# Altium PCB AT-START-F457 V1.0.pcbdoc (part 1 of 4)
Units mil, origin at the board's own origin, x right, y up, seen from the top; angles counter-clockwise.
Board outline 11593.57 x 3554 mil, 2 copper layers (Top Layer, Bottom Layer); 196 components, 231 nets, 905 pads, 932 vias.
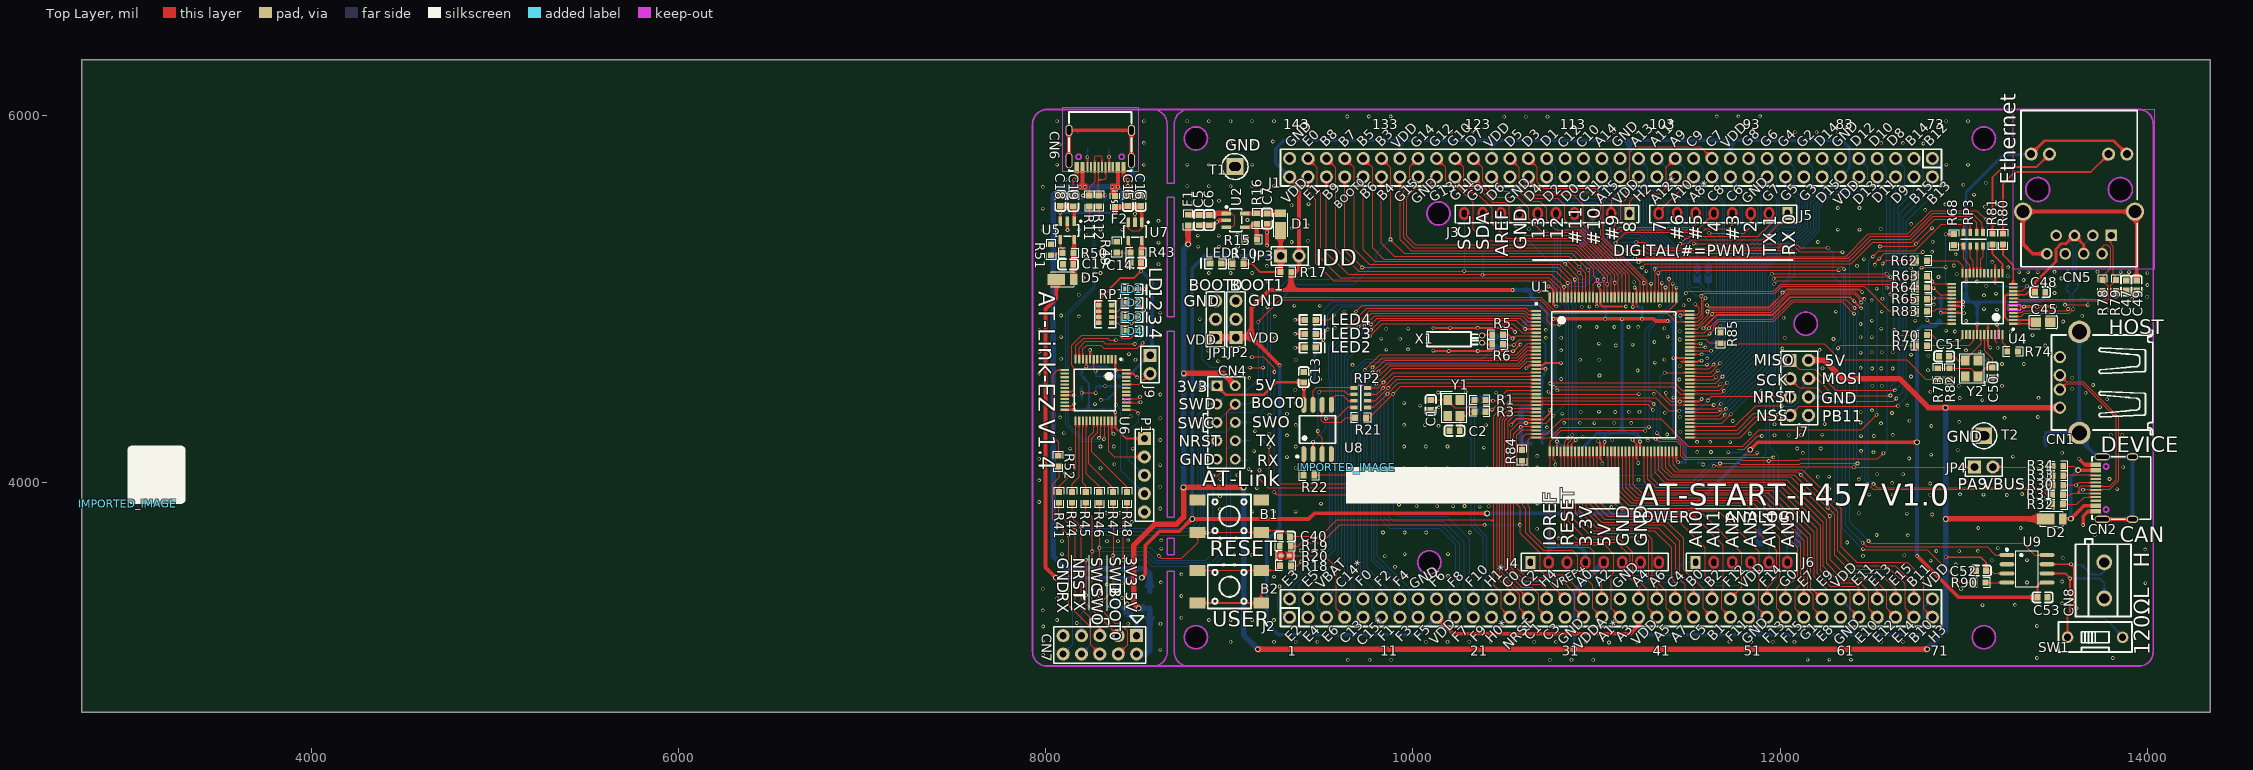
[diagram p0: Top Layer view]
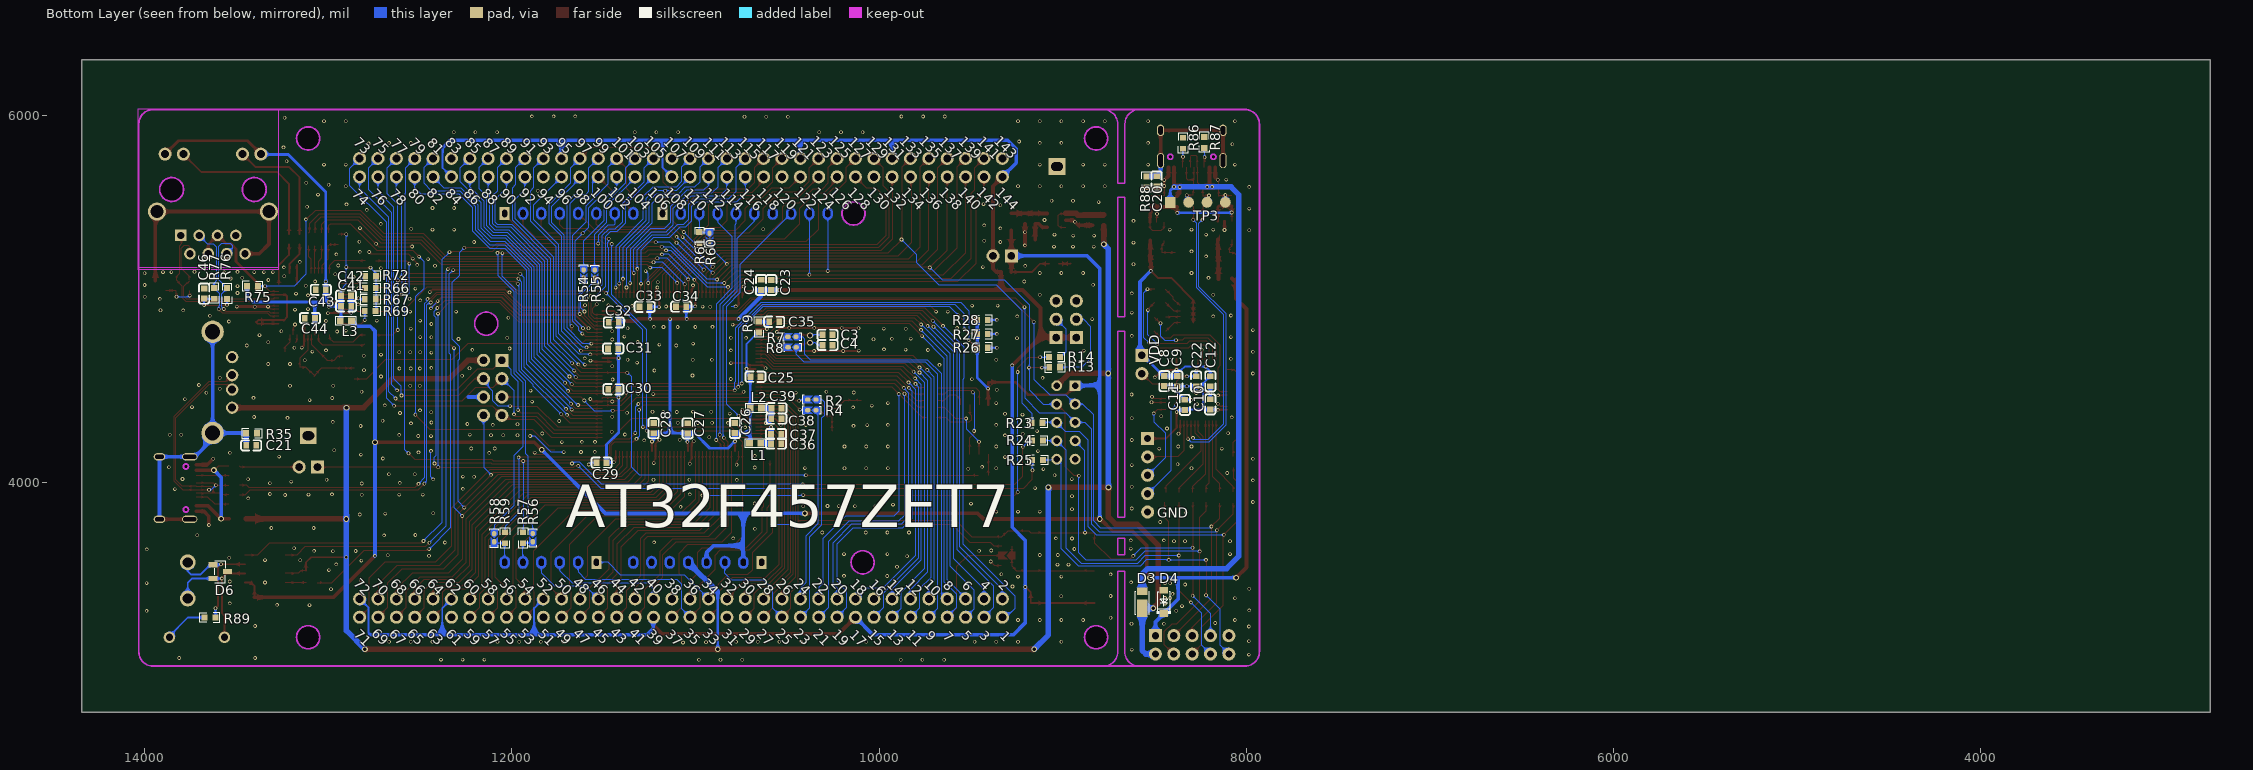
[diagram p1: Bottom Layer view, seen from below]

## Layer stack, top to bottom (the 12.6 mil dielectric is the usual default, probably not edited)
Top Layer: signal copper (thickness not stored)
Dielectric: dielectric 12.6, FR-4, Dk 4.8
Bottom Layer: signal copper (thickness not stored)

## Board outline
14343.57,2750 2750,2750 2750,6304 14343.57,6304
cut-out: 12202.8,4865.97 ccw(c12139.81,4865.43) 12076.82,4865.97 ccw(c12139.81,4866.51)
cut-out: 10202.8,5465.96 ccw(c10139.81,5465.42) 10076.82,5465.96 ccw(c10139.81,5466.5)
cut-out: 10152.8,3565.97 ccw(c10089.81,3565.43) 10026.82,3565.97 ccw(c10089.81,3566.51)
cut-out: 8881.38,5874.63 ccw(c8818.39,5874.09) 8755.4,5874.63 ccw(c8818.39,5875.17)
cut-out: 8881.38,3158.09 ccw(c8818.39,3157.55) 8755.4,3158.09 ccw(c8818.39,3158.63)
cut-out: 13172.72,3158.09 ccw(c13109.73,3157.55) 13046.74,3158.09 ccw(c13109.73,3158.63)
cut-out: 13172.72,5874.63 ccw(c13109.73,5874.09) 13046.74,5874.63 ccw(c13109.73,5875.17)

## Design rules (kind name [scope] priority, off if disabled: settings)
BoardOutlineClearance copperThickness1oz [All] p0: genericclearance=10 ignorepadtopadclearanceinfootprint=FALSE except(0: Arc-SplitContinuation Track-SplitContinuation SMDPad-SplitContinuation THPad-SplitContinuation Via-SplitContinuation Fill-SplitContinuation Poly-SplitContinuation Region-SplitContinuation Text-SplitContinuation; 6: SMDPad-CutoutEdge THPad-CutoutEdge Via-CutoutEdge Fill-CutoutEdge Region-CutoutEdge; 11.8: Track-OutlineEdge SMDPad-OutlineEdge THPad-OutlineEdge Via-OutlineEdge Fill-OutlineEdge Region-OutlineEdge Poly-OutlineEdge Text-OutlineEdge Track-CutoutEdge)
Clearance copperThickness1oz [(InNet('GND') OR InNet('PB11') OR InNet('PD4') OR InNet('PA1') OR InNet('PC1') OR InNet('PE15') OR InNet('PB10') OR InNet('PG6') OR InNet('PD10') OR InNet('PD9') OR InNet('PD8') OR InNet('PG15') OR InNet('PA2') OR InNet('PC0') OR InNet('PC2') OR InNet('NRST') OR InNet('PA15') OR InNet('PA13/SWDIO') OR InNet('PA14/SWCLK') OR InNet('VDD') OR InNet('PA3') OR InNet('PB2/BOOT1') OR InNet('3V3') OR InNet('PA0') OR InNet('PA5') OR InNet('PA6') OR InNet('PA7') OR InNet('PA9') OR InNet('PA10') OR InNet('3V3_EMAC') OR InNet('RX+') OR InNet('RX-') OR InNet('PG14') OR InNet('PG13') OR InNet('PG11') OR InNet('PB5') OR InNet('PB6') OR InNet('PD2') OR InNet('PC12') OR InNet('PC11') OR InNet('PC10') OR InNet('VBAT') OR InNet('VDDA') OR InNet('VREF+') OR InNet('PD11') OR InNet('PD12') OR InNet('PD13') OR InNet('PD14') OR InNet('PD15') OR InNet('PG2') OR InNet('PG3') OR InNet('PG4') OR InNet('PG5') OR InNet('PG7') OR InNet('PG8') OR InNet('PC6') OR InNet('PC7') OR InNet('PC8') OR InNet('PC9') OR InNet('PA8') OR InNet('PH2') OR InNet('PH0/HEXT_IN') OR InNet('PH1/HEXT_OUT') OR InNet('PF10') OR InNet('PF9') OR InNet('PF8') OR InNet('PF7') OR InNet('PF6') OR InNet('PF5') OR InNet('PF4') OR InNet('PF3') OR InNet('PF2') OR InNet('PF1') OR InNet('PF0') OR InNet('PC13') OR InNet('PE6') OR InNet('PE5') OR InNet('PE4') OR InNet('PE3') OR InNet('PE2') OR InNet('PC15/LEXT_OUT') OR InNet('PC14/LEXT_IN') OR InNet('SWO') OR InNet('ATLK_RX') OR InNet('LD4') OR InNet('VCC') OR InNet('M-NRST') OR InNet('ATLK_TX') OR InNet('ATLINK_5V') OR InNet('PH3') OR InNet('PB3') OR InNet('QSPI1_IO2') OR InNet('QSPI1_IO1') OR InNet('PB4') OR InNet('PH1_E') OR InNet('PH0_E') OR InNet('PC15_E') OR InNet('PC14_E') OR InNet('PA11_E') OR InNet('PA12_E') OR InNet('PB0') OR InNet('PA4') OR InNet('PE10') OR InNet('PC4') OR InNet('VCC3.5V') OR InNet('PG0') OR InNet('PE7') OR InNet('PE8') OR InNet('PG1') OR InNet('LD3') OR InNet('LD2') OR InNet('LD1') OR InNet('AVDD18') OR InNet('EMAC_NRST') OR InNet('TX+') OR InNet('PD3') OR InNet('PG9') OR InNet('PD6') OR InNet('REF_CLK') OR InNet('TXEN') OR InNet('TXD0') OR InNet('TXD1') OR InNet('XT1') OR InNet('RXD0') OR InNet('RXD1') OR InNet('MDIO') OR InNet('M-SWDIO') OR InNet('M-ATLK_RX') OR InNet('M-ATLK_TX') OR InNet('PE1') OR InNet('TX-') OR InNet('PC3') OR InNet('PD7') OR InNet('PG10') OR InNet('PG12') OR InNet('LED_G') OR InNet('LED_Y') OR InNet('EMAC_GND') OR InNet('M-SWCLK') OR InNet('CRS_DV') OR InNet('PC5') OR InNet('PE12') OR InNet('PE11') OR InNet('PF15') OR InNet('PF14') OR InNet('PE13') OR InNet('PE14') OR InNet('PE9') OR InNet('PF12') OR InNet('PF13') OR InNet('PB1') OR InNet('PD5') OR InNet('PE0') OR InNet('QSPI1_SCK') OR InNet('PF11') OR InNet('QSPI1_IO0') OR InNet('QSPI1_IO3') OR InNet('$2N452') OR InNet('$2N453') OR InNet('$2N511') OR InNet('$2N512') OR InNet('$2N702') OR InNet('$2N701') OR InNet('$3N82') OR InNet('$3N81') OR InNet('$3N119') OR InNet('$3N184') OR InNet('$3N504') OR InNet('$3N505') OR InNet('$3N506') OR InNet('$4N269') OR InNet('$4N270') OR InNet('$4N339') OR InNet('$5N126') OR InNet('$5N184') OR InNet('$5N573') OR InNet('$5N285') OR InNet('$5N306') OR InNet('$5N309') OR InNet('$5N310') OR InNet('$3N58') OR InNet('PA8_E') OR InNet('PA1_E') OR InNet('XT2') OR InNet('MDINTR') OR InNet('EGND1') OR InNet('OTGFS1_D-') OR InNet('OTGFS1_D+') OR InNet('PB12') OR InNet('PB13') OR InNet('PB14') OR InNet('PB15') OR InNet('PH4') OR InNet('QSPI1_CS') OR InNet('$3N17593') OR InNet('ATLK_SWCLK') OR InNet('$6N17598') OR InNet('ATLK_SWDIO') OR InNet('ATLK_BOOT0') OR InNet('ATLK_NRST') OR InNet('$6N17675') OR InNet('ATLK_SWO') OR InNet('PA11') OR InNet('PA12') OR InNet('$6N16959') OR InNet('EGND') OR InNet('$3N17443') OR InNet('$3N17484') OR InNet('CC2') OR InNet('USBP') OR InNet('USBM') OR InNet('CC1') OR InNet('M-BOOT0') OR InNet('$6N792') OR InNet('$6N793') OR InNet('$6N794') OR InNet('$6N795') OR InNet('M-USB_DP') OR InNet('M-USB_DM') OR InNet('5V') OR InNet('BOOT0') OR InNet('CAN1_STB') OR InNet('CAN1_RX') OR InNet('CAN1_TX') OR InNet('CAN_L') OR InNet('CAN_H') OR InNet('$3N21100') OR InNet('$3N21099') OR InNet('PB8') OR InNet('PB9') OR InNet('VBUS'))] p1: gap=7 ignorepadtopadclearanceinfootprint=FALSE except(6: Track-Track Track-SMDPad SMDPad-SMDPad Track-THPad SMDPad-THPad THPad-THPad Track-Via SMDPad-Via THPad-Via Via-Via Track-Fill SMDPad-Fill THPad-Fill Via-Fill Fill-Fill SMDPad-Region THPad-Region Via-Region Fill-Region Region-Region Track-Poly SMDPad-Poly THPad-Poly Via-Poly Fill-Poly Poly-Poly Track-Text SMDPad-Text THPad-Text Via-Text Fill-Text Region-Text Poly-Text Text-Text; 6.9: Track-Hole SMDPad-Hole THPad-Hole Via-Hole Fill-Hole Region-Hole Poly-Hole Text-Hole Sheet-Hole; 11.8: Track-Region Region-Poly Track-Sheet SMDPad-Sheet THPad-Sheet Via-Sheet Fill-Sheet Region-Sheet Poly-Sheet Text-Sheet)
DiffPairsRouting differentialPair [All] p1: maxuncoupledlength=10 minlimit=5.9843 maxlimit=5.9843 mostfreqgap=5.9843 toplayer_minwidth=5 toplayer_prefwidth=10 toplayer_maxwidth=100 bottomlayer_minwidth=5 bottomlayer_prefwidth=10 bottomlayer_maxwidth=100
PasteMaskExpansion pasteMaskExpansion [All] p1: expansion=0
PlaneConnect innerPlane [All] p1: planeconnectstyle=Relief reliefexpansion=20 reliefentries=4 reliefconductorwidth=10 reliefairgap=10
PolygonConnect copperRegion [All] p1: connectstyle=Relief reliefentries=4 reliefconductorwidth=10 polygonreliefangle="90 Angle" airgapwidth=10
RoutingVias viaSize [All] p1: viastyle="Through Hole" holewidth=11.811 minholewidth=11.811 maxholewidth=19.685 width=19.685 minwidth=19.685 maxwidth=31.496
SolderMaskExpansion solderMaskExpansion [All] p1: useseparateexpansions=TRUE expansion=2.0079 expansionbottom=2.0079
Width copperThickness1oz [All] p1: maxlimit=100 minlimit=6 preferedwidth=6

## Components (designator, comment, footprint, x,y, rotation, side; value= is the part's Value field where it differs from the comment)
B1 "贴片按键6*6*5 黑色" SW-SMD_4P-L6.0-W6.0-P4.50-LS9.0 9001.26,3816.97 r180 top
B2 "贴片按键6*6*5 红色" SW-SMD_4P-L6.0-W6.0-P4.50-LS9.0 9001.26,3432.97 r180 top
C1 "CL10C150JB8NNNC" C0603 10097.57,4422.61 r90 top
C2 "CL10C150JB8NNNC" C0603 10227.57,4282.61 r0 top
C3 "CL10C180JB8NNNC" C0603 10281.06,4805.16 r0 bottom
C4 "CL10C180JB8NNNC" C0603 10281.07,4749.61 r0 bottom
C5 "CL10A106KP8NNNC" C0603 8836.21,5429.61 r270 top
C6 "CC0603KRX7R9BB104" C0603 8891.21,5429.61 r270 top
C7 "CL10A106KP8NNNC" C0603 9206.21,5437.97 r270 top
C8 "CL10A475KO8NNNC" C0603 8446.37,4553.41 r90 bottom
C9 "CC0603KRX7R9BB104" C0603 8376.37,4552.61 r90 bottom
C10 "CC0603KRX7R9BB104" C0603 8196.77,4426.21 r270 bottom
C11 "CC0603KRX7R9BB104" C0603 8335.17,4423.41 r270 bottom
C12 "CC0603KRX7R9BB104" C0603 8196.37,4552.21 r90 bottom
C13 "CC0603KRX7R9BB104" C0603 9406.18,4574.85 r90 top
C14 "CL10A106KP8NNNC" C0603 8491.81,5197.16 r0 top
C15 "CL10A106KP8NNNC" C0603 8448.56,5534.05 r270 top
C16 "CC0603KRX7R9BB104" C0603 8517.56,5534.05 r270 top
C17 "CL10A106KP8NNNC" C0603 8122.56,5189.05 r0 top
C18 "CL10A106KP8NNNC" C0603 8080.37,5533.81 r270 top
C19 "CC0603KRX7R9BB104" C0603 8150.37,5533.01 r270 top
C20 "CC0603KRX7R9BB104" C0603 8489.57,5640.61 r90 bottom
C21 "CC0603KRX7R9BB104" C0603 13419.56,4202.84 r180 bottom
C22 "CC0603KRX7R9BB104" C0603 8273.97,4552.21 r90 bottom
C23 "CL10A475KO8NNNC" C0603 10587.57,5076.61 r90 bottom
C24 "CC0603KRX7R9BB104" C0603 10643.21,5076.97 r90 bottom
C25 "CC0603KRX7R9BB104" C0603 10673.21,4576.97 r180 bottom
C26 "CC0603KRX7R9BB104" C0603 10785.21,4297.97 r90 bottom
C27 "CC0603KRX7R9BB104" C0603 11043.21,4295.97 r90 bottom
C28 "CC0603KRX7R9BB104" C0603 11228.21,4296.97 r90 bottom
C29 "CC0603KRX7R9BB104" C0603 11512,4109.02 r0 bottom
C30 "CC0603KRX7R9BB104" C0603 11447.57,4508.61 r0 bottom
C31 "CC0603KRX7R9BB104" C0603 11448.57,4730.61 r0 bottom
C32 "CC0603KRX7R9BB104" C0603 11445.57,4872.61 r0 bottom
C33 "CC0603KRX7R9BB104" C0603 11277.21,4957.97 r0 bottom
C34 "CC0603KRX7R9BB104" C0603 11078.21,4958.97 r0 bottom
C35 "CC0603KRX7R9BB104" C0603 10571.21,4875.97 r180 bottom
C36 "CL10A105KB8NNNC" C0603 10561.21,4212.97 r180 bottom
C37 "CC0603KRX7R9BB104" C0603 10561.21,4264.97 r180 bottom
C38 "CC0603KRX7R9BB104" C0603 10559.57,4348.61 r180 bottom
C39 "CL10A105KB8NNNC" C0603 10559.21,4404.97 r180 bottom
C40 "CC0603KRX7R9BB104" C0603 9304.21,3705.97 r180 top
C41 "CL10A106KP8NNNC" C0603 12902.66,4960.31 r180 bottom
C42 "CC0603KRX7R9BB104" C0603 12903.3,5017.89 r180 bottom
C43 "CC0603KRX7R9BB104" C0603 13041.21,5049.97 r0 bottom
C44 "CC0603KRX7R9BB104" C0603 13100.21,4895.97 r0 bottom
C45 "CL21A476MQYNNNE" C0805 13432.45,4874.14 r180 top
C46 "CC0603KRX7R9BB104" C0603 13676.49,5030.11 r90 bottom
C47 "CC0603KRX7R9BB104" C0603 13884.53,5073.84 r90 top
C48 "CC0603KRX7R9BB104" C0603 13416.21,5037.97 r180 top
C49 "CC0603KRX7R9BB104" C0603 13941.66,5073.84 r90 top
C50 "CL10C150JB8NNNC" C0603 13156.37,4600.21 r270 top
C51 "CL10C150JB8NNNC" C0603 12893.17,4688.21 r180 top
C52 "CC0603KRX7R9BB104" C0603 13094.57,3520.61 r0 top
C53 "CC0603KRX7R9BB104" C0603 13429.57,3375.61 r180 top
CN1 "JTJ-USB-AF-08" USB-A-TH__USB-AF-90 13576.84,4545.91 r90 top
CN2 "TYPEC-304-BCP16" USB-C-SMD_TYPEC-304-BCP16#1 13819.11,3970.73 r90 top
CN4 "CON10A_0" HDR2X5#1 8933.23,4527.98 r270 top
CN5 "RJ45(TRJ201)" RJ45-TH_HR911105A 13628.26,5517.93 r180 top
CN6 "TYPEC-304-BCP16" USB-C-SMD_TYPEC-304-BCP16#2 8297.21,5818.2 r180 top locked
CN7 "CON10" HDR2X5#2 8495.46,3166.58 r180 top
CN8 "KF301-5.0-2P" CONN-TH_P5.00_KF301-5.0-2P 13765.59,3467.73 r90 top locked
D1 "DFLS130L-7" POWERDI-123_L2.8-W1.8-LS3.7-RD 9280.21,5419.98 r90 top
D2 "DFLS130L-7" POWERDI-123_L2.8-W1.8-LS3.7-RD 13492.74,3802.96 r0 top
D3 "DFLS130L-7" POWERDI-123_L2.8-W1.8-LS3.7-RD 8567.57,3362.61 r90 bottom
D4 "SMF3.3A_C2759873" SOD-123FL_L2.8-W1.8-LS3.8-RD 8449.57,3350.61 r90 bottom
D5 "DFLS130L-7" POWERDI-123_L2.8-W1.8-LS3.7-RD 8105.61,5107.05 r0 top
D6 "PESD2CANFD24V-TR" SOT-23-3_L2.9-W1.3-P1.90-LS2.4-BR 13589.57,3515.61 r0 bottom
F1 "SMD0603B050TF" R0603 8776.26,5429.58 r90 top
F2 "BSMD0603-050-6V" F0603 8377.56,5531.05 r270 top
IMPORTED_IMAGE "IMPORTED_IMAGE" IMPORTED_IMAGE 3000,3885.66 r0 top
IMPORTED_IMAGE "IMPORTED_IMAGE" IMPORTED_IMAGE 9636.42,4083.65 r0 top
J1 "HDR 2X36" HDR_2.54_2X36 11079.18,5715.65 r180 top locked
J2 "HDR 2X36" HDR_2.54_2X36 11079.18,3317.07 r0 top locked
J3 "CON10" "FEMALE HEADER 1X10" 10729.8,5465.97 r0 top locked
J4 "CON8" "FEMALE HEADER 1X8" 10989.8,3565.97 r0 top locked
J5 "CON8" "FEMALE HEADER 1X8" 11689.8,5465.97 r180 top locked
J6 "CON6" "FEMALE HEADER 1X6" 11789.8,3565.97 r0 top locked
J7 "Header 4X2" HDR2X4 12054.8,4666.56 r270 top locked
J9 "1X2P_2.54M" HDR1X2 8569.46,4693.58 r270 top
JP1 "Jumper 1x3P" "HEADER 1X3" 8926.21,4789.97 r90 top
JP2 "Jumper 1x3P" "HEADER 1X3" 9036.21,4789.97 r90 top
JP3 "Jumper 1x2P" "HEADER 1X2" 9280.21,5234.97 r0 top
JP4 "Jumper 1x2P" "HEADER 1X2" 13058.9,4085.21 r0 top
L1 "0.5A,600Ω@100Mhz" 0603_L 10675.26,4214.98 r180 bottom
L2 "0.5A,600Ω@100Mhz" 0603_L 10671.57,4406.61 r180 bottom
L3 "0.5A,600Ω@100Mhz" 0603_L 12904.2,4881.03 r0 bottom
LD1 "RED" LED0603 8439.47,5052.43 r0 top
LD2 "GREEN" LED0603 8440.43,4978.33 r0 top
LD3 "BLUE" LED0603 8440.47,4901.43 r0 top
LD4 "YELLOW" LED0603 8440.43,4825.43 r0 top
LED1 "RED" LED0603 8956.21,5192.97 r180 top
LED2 "RED" LED0603 9411.05,4735 r0 top
LED3 "YELLOW" LED0603 9411.06,4809.98 r0 top
LED4 "GREEN" LED0603 9411.06,4886.28 r0 top
P1 "Header 5" HDR1X5 8538.16,4240.18 r270 top
R1 "0603WAF0000T5E" R0603 10365.57,4450.61 r0 top
R2 "NC" SB-PAD 10367.57,4452.61 r0 bottom
R3 "0603WAF0000T5E" R0603 10365.57,4386.61 r0 top
R4 "NC" SB-PAD 10367.57,4394.61 r0 bottom
R5 "0603WAF0000T5E" R0603 10462.2,4805.92 r0 top
R6 "0603WAF0000T5E" R0603 10462.2,4753.19 r0 top
R7 "NC" SB-PAD 10475.65,4794.53 r0 bottom
R8 "NC" SB-PAD 10474.95,4737.01 r0 bottom
R9 "0603WAF0000T5E" R0603 10655.21,4847.97 r270 bottom
R10 "0603WAF1001T5E" R0603 9048.26,5191.98 r180 top
R11 "0603WAF0000T5E" R0603 8238.07,5534.03 r270 top
R12 "0603WAF0000T5E" R0603 8290.08,5534.82 r270 top
R13 "0603WAF1002T5E" R0603 9044.21,4627.97 r0 bottom
R14 "0603WAF1002T5E" R0603 9045.21,4683.97 r0 bottom
R15 "0603WAF1502T5E" R0603 9122.21,5323.97 r180 top
R16 "0603WAF5102T5E" R0603 9150.21,5437.97 r90 top
R17 "0603WAF0000T5E" R0603 9308.21,5146.97 r0 top
R18 "0603WAF1003T5E" R0603 9306.21,3547.97 r180 top
R19 "0603WAF0000T5E" R0603 9305.21,3653.97 r0 top
R20 "NC" SB-PAD 9305.21,3602.97 r0 top
R21 "0603WAF330JT5E" R0603 9715.18,4353.85 r180 top
R22 "0603WAF330JT5E" R0603 9433.51,4039.99 r180 top
R23 "0603WAF4700T5E" R0603 9140.26,4325.98 r0 bottom
R24 "0603WAF4700T5E" R0603 9138.26,4229.98 r0 bottom
R25 "0603WAF4700T5E" R0603 9137.66,4123.08 r0 bottom
R26 "0603WAF1001T5E" R0603 9437.86,4735 r180 bottom
R27 "0603WAF1001T5E" R0603 9437.86,4810 r180 bottom
R28 "0603WAF1001T5E" R0603 9437.86,4886.3 r180 bottom
R30 "0603WAF0000T5E" R0603 13512.57,3985.61 r0 top
R31 "0603WAF0000T5E" R0603 13511.57,3933.61 r0 top
R32 "0603WAF5101T5E" R0603 13511.99,3881.81 r0 top
R33 "0603WAF5101T5E" R0603 13512.77,4038.23 r0 top
R34 "0603WAF1002T5E" R0603 13512.77,4090.63 r0 top
R35 "RC0603FR-071ML" R0603 13417.73,4268.59 r0 bottom
R41 "0603WAF330JT5E" R0603 8073.66,3920.18 r270 top
R43 "0603WAF4702T5E" R0603 8491.56,5253.41 r180 top
R44 "0603WAF330JT5E" R0603 8143.66,3920.18 r270 top
R45 "0603WAF330JT5E" R0603 8218.66,3920.18 r270 top
R46 "0603WAF330JT5E" R0603 8292.66,3920.18 r270 top
R47 "0603WAF330JT5E" R0603 8367.66,3920.18 r270 top
R48 "0603WAF330JT5E" R0603 8443.66,3920.18 r270 top
R49 "0603WAF1502T5E" R0603 8387.57,5282.61 r90 top
R50 "0603WAF5102T5E" R0603 8122.56,5251.05 r180 top
R51 "0603WAF1502T5E" R0603 8029.57,5268.61 r90 top
R52 "0603WAF330JT5E" R0603 8068.66,4117.18 r270 top
R54 "NC" SB-PAD 11609.39,5135.54 r270 bottom
R55 "NC" SB-PAD 11549.03,5134.76 r270 bottom
R56 "NC" SB-PAD 11886.21,3699.97 r270 bottom
R57 "0603WAF0000T5E" R0603 11940.21,3699.97 r270 bottom
R58 "NC" SB-PAD 12096.95,3699.18 r270 bottom
R59 "0603WAF0000T5E" R0603 12037.06,3699.96 r270 bottom
R60 "NC" SB-PAD 10923.85,5335.18 r270 bottom
R61 "0603WAF0000T5E" R0603 10979.21,5334.97 r90 bottom
R62 "0603WAF330JT5E" R0603 12770.21,5209.08 r0 top
R63 "0603WAF330JT5E" R0603 12771.08,5123.88 r0 top
R64 "0603WAF330JT5E" R0603 12771.08,5062.81 r0 top
R65 "0603WAF330JT5E" R0603 12771.08,4998.98 r0 top
R66 "0603WAF4701T5E" R0603 12770.85,5060.32 r0 bottom
R67 "0603WAF4701T5E" R0603 12771.48,4998.59 r0 bottom
R68 "0603WAF4701T5E" R0603 12946.21,5323.97 r270 top
R69 "0603WAF4701T5E" R0603 12771.87,4935.15 r0 bottom
R70 "0603WAF330JT5E" R0603 12770.85,4804.32 r0 top
R71 "0603WAF330JT5E" R0603 12770.21,4745.97 r0 top
R72 "0603WAF1501T5E" R0603 12769.11,5124.27 r180 bottom
R73 "0603WAF330JT5E" R0603 12858.77,4593.81 r90 top
R74 "0603WAF6801T5E" R0603 13266.77,4713.81 r180 top
R75 "0603WAF4701T5E" R0603 13413.26,5069.98 r0 bottom
R76 "0603WAF499JT5E" R0603 13552.21,5029.97 r90 bottom
R77 "0603WAF499JT5E" R0603 13621.73,5030.9 r90 bottom
R78 "0603WAF499JT5E" R0603 13756.08,5074.24 r90 top
R79 "0603WAF499JT5E" R0603 13829.37,5074.24 r90 top
R80 "0603WAF4700T5E" R0603 13214.21,5325.97 r270 top
R81 "0603WAF4700T5E" R0603 13156.21,5325.97 r270 top
R82 "0603WAF1003T5E" R0603 12922.37,4593.01 r270 top
R83 "0603WAF330JT5E" R0603 12771.08,4933.58 r0 top
R84 "0603WAF0000T5E" R0603 10594.63,4148.73 r90 top
R85 "0603WAF0000T5E" R0603 11675.37,4788.98 r270 top
R86 "0603WAF5101T5E" R0603 8345.57,5848.61 r90 bottom
R87 "0603WAF5101T5E" R0603 8229.57,5852.61 r90 bottom
R88 "RC0603FR-071ML" R0603 8543.57,5638.61 r270 bottom
R89 "0603WAF1200T5E" R0603 13644.57,3265.61 r180 bottom
R90 "0603WAF3300T5E" R0603 13089.57,3455.61 r0 top
RP1 "4D03WGJ0102T5E" RES-ARRAY-SMD_0603-8P-L3.2-W1.6-BL 8324.77,4918.21 r270 top
RP2 "33R" 0603*4,8P4R 9753.18,4409.85 r90 top
RP3 "33R" 0603*4,8P4R 13106.21,5361.97 r180 top
SW1 "DSWB01LHGET" SW-TH_DSWB01LHGET 13715.56,3157.52 r90 top locked
T1 "TESTPOINT TP-5006" TESTHOOK 9031.47,5721.74 r0 top
T2 "TESTPOINT TP-5006" TESTHOOK 13108.6,4255.65 r0 top
TP3 "1X4P_2.54F" "HDR1X4 - TOP" 8414.58,5526.61 r0 bottom
U1 "AT32F457ZET7" LQFP144_20*20 11090.17,4589.99 r0 top locked
U2 "RT9080N-08GJ5" SOT-23-5 9049.21,5365.97 r0 top
U4 "DM9162EP" LQFP48_7*7 13102.21,4973.97 r180 top locked
U5 "RT9080N-08GJ5" SOT-23-5 8055.56,5359.05 r270 top
U6 "AT32F403ACCT7" "LQFP48 - 2" 8380.17,4672.63 r270 top locked
U7 "RT9080N-08GJ5" SOT-23-5 8424.34,5353.39 r270 top
U8 "EN25QH128A-104HIP" SOIC-8_208MIL 9481.16,4289.78 r0 top locked
U9 "MCP2562FD-E/SN" SOIC-8_L4.9-W3.9-P1.27-LS6.0-BL 13344.57,3530.61 r270 top
X1 "X206032768KGB2SC" OSC-TH_BD2.0-P0.70-D0.3 10376.57,4781.61 r0 top
Y1 "CJ13-080001210B20" CRYSTAL-SMD_4P-L3.2-W2.5-BL 10223.57,4406.61 r270 top
Y2 "X322525MOB4SI" OSC-SMD_4P-L3.2-W2.5-BL 13043.17,4621.81 r90 top

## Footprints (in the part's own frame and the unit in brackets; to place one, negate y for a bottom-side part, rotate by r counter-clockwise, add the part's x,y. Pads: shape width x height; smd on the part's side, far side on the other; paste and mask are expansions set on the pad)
0603*4,8P4R [mm]
  rect 0.55x0.95 smd: 1(0,0) 4(2.7,0) 5(2.7,1.85) 8(0,1.85)
  rect 0.5x0.95 smd: 2(0.9,0) 3(1.8,0) 6(1.8,1.85) 7(0.9,1.85)
  silkscreen extent -0.43,0.94 3.1,0.94
0603_L [mm]
  rect 0.93x0.9 smd: 1(-0.77,0) 2(0.77,0)
  silkscreen extent -1.4,-0.64 1.4,0.64
C0603 [mm]
  rect 0.8x0.9 smd: 1(-0.7,0) 2(0.7,0)
  silkscreen extent -1.41,-0.71 1.39,0.72
C0805 [mm]
  rect 1.41x1.35 smd: 1(-1,0) 2(1,0)
  silkscreen extent -1.96,-0.9 1.96,0.9
CONN-TH_P5.00_KF301-5.0-2P [mm]
  round 2.2 hole 1.4: 1(-2.5,0) 2(2.5,0)
  silkscreen extent -5,-3.7 5.71,4
CRYSTAL-SMD_4P-L3.2-W2.5-BL [mm]
  rect 1.4x1.2 smd: 1(-1.1,-0.85) 2(1.1,-0.85) 3(1.1,0.85) 4(-1.1,0.85)
  silkscreen extent -2.26,-1.91 2.03,1.68
F0603 [mil]
  rect 31.75x34.02 smd: 1(-29.66,0) 2(29.66,0)
  silkscreen extent -55,-25 55,25
"FEMALE HEADER 1X6" [mm]
  rect 1.4x1.8 hole 0.7 slot 1 at 90 deg: 1(-6.35,0)
  oval 0.6x0.42 hole 0.7 slot 1 at 90 deg: 2(-3.81,0) 3(-1.27,0) 4(1.27,0) 5(3.81,0) 6(6.35,0)
  Top Layer region: 7.05,-0.2 6.956,-0.55 6.7,-0.806 6.35,-0.9 6,-0.806 5.744,-0.55 5.65,-0.2 5.65,0.2 5.744,0.55 6,0.806 6.35,0.9 6.7,0.806 6.956,0.55 7.05,0.2
  Top Layer region: 4.51,-0.2 4.416,-0.55 4.16,-0.806 3.81,-0.9 3.46,-0.806 3.204,-0.55 3.11,-0.2 3.11,0.2 3.204,0.55 3.46,0.806 3.81,0.9 4.16,0.806 4.416,0.55 4.51,0.2
  Top Layer region: 1.97,-0.2 1.876,-0.55 1.62,-0.806 1.27,-0.9 0.92,-0.806 0.664,-0.55 0.57,-0.2 0.57,0.2 0.664,0.55 0.92,0.806 1.27,0.9 1.62,0.806 1.876,0.55 1.97,0.2
  Top Layer region: -0.57,-0.2 -0.664,-0.55 -0.92,-0.806 -1.27,-0.9 -1.62,-0.806 -1.876,-0.55 -1.97,-0.2 -1.97,0.2 -1.876,0.55 -1.62,0.806 -1.27,0.9 -0.92,0.806 -0.664,0.55 -0.57,0.2
  Top Layer region: -3.11,-0.2 -3.204,-0.55 -3.46,-0.806 -3.81,-0.9 -4.16,-0.806 -4.416,-0.55 -4.51,-0.2 -4.51,0.2 -4.416,0.55 -4.16,0.806 -3.81,0.9 -3.46,0.806 -3.204,0.55 -3.11,0.2
  Bottom Layer region: 7.05,-0.2 6.956,-0.55 6.7,-0.806 6.35,-0.9 6,-0.806 5.744,-0.55 5.65,-0.2 5.65,0.2 5.744,0.55 6,0.806 6.35,0.9 6.7,0.806 6.956,0.55 7.05,0.2
  Bottom Layer region: 4.51,-0.2 4.416,-0.55 4.16,-0.806 3.81,-0.9 3.46,-0.806 3.204,-0.55 3.11,-0.2 3.11,0.2 3.204,0.55 3.46,0.806 3.81,0.9 4.16,0.806 4.416,0.55 4.51,0.2
  Bottom Layer region: 1.97,-0.2 1.876,-0.55 1.62,-0.806 1.27,-0.9 0.92,-0.806 0.664,-0.55 0.57,-0.2 0.57,0.2 0.664,0.55 0.92,0.806 1.27,0.9 1.62,0.806 1.876,0.55 1.97,0.2
  Bottom Layer region: -0.57,-0.2 -0.664,-0.55 -0.92,-0.806 -1.27,-0.9 -1.62,-0.806 -1.876,-0.55 -1.97,-0.2 -1.97,0.2 -1.876,0.55 -1.62,0.806 -1.27,0.9 -0.92,0.806 -0.664,0.55 -0.57,0.2
  Bottom Layer region: -3.11,-0.2 -3.204,-0.55 -3.46,-0.806 -3.81,-0.9 -4.16,-0.806 -4.416,-0.55 -4.51,-0.2 -4.51,0.2 -4.416,0.55 -4.16,0.806 -3.81,0.9 -3.46,0.806 -3.204,0.55 -3.11,0.2
  Multi-Layer region: 7.05,-0.2 6.956,-0.55 6.7,-0.806 6.35,-0.9 6,-0.806 5.744,-0.55 5.65,-0.2 5.65,0.2 5.744,0.55 6,0.806 6.35,0.9 6.7,0.806 6.956,0.55 7.05,0.2
  Multi-Layer region: 4.51,-0.2 4.416,-0.55 4.16,-0.806 3.81,-0.9 3.46,-0.806 3.204,-0.55 3.11,-0.2 3.11,0.2 3.204,0.55 3.46,0.806 3.81,0.9 4.16,0.806 4.416,0.55 4.51,0.2
  Multi-Layer region: 1.97,-0.2 1.876,-0.55 1.62,-0.806 1.27,-0.9 0.92,-0.806 0.664,-0.55 0.57,-0.2 0.57,0.2 0.664,0.55 0.92,0.806 1.27,0.9 1.62,0.806 1.876,0.55 1.97,0.2
  Multi-Layer region: -0.57,-0.2 -0.664,-0.55 -0.92,-0.806 -1.27,-0.9 -1.62,-0.806 -1.876,-0.55 -1.97,-0.2 -1.97,0.2 -1.876,0.55 -1.62,0.806 -1.27,0.9 -0.92,0.806 -0.664,0.55 -0.57,0.2
  Multi-Layer region: -3.11,-0.2 -3.204,-0.55 -3.46,-0.806 -3.81,-0.9 -4.16,-0.806 -4.416,-0.55 -4.51,-0.2 -4.51,0.2 -4.416,0.55 -4.16,0.806 -3.81,0.9 -3.46,0.806 -3.204,0.55 -3.11,0.2
  silkscreen extent -7.62,-1.17 7.62,1.27
"FEMALE HEADER 1X8" [mm]
  rect 1.4x1.8 hole 0.7 slot 1 at 90 deg: 1(-8.89,0)
  oval 0.6x0.42 hole 0.7 slot 1 at 90 deg: 2(-6.35,0) 3(-3.81,0) 4(-1.27,0) 5(1.27,0) 6(3.81,0) 7(6.35,0) 8(8.89,0)
  Top Layer region: 9.59,-0.2 9.496,-0.55 9.24,-0.806 8.89,-0.9 8.54,-0.806 8.284,-0.55 8.19,-0.2 8.19,0.2 8.284,0.55 8.54,0.806 8.89,0.9 9.24,0.806 9.496,0.55 9.59,0.2
  Top Layer region: 7.05,-0.2 6.956,-0.55 6.7,-0.806 6.35,-0.9 6,-0.806 5.744,-0.55 5.65,-0.2 5.65,0.2 5.744,0.55 6,0.806 6.35,0.9 6.7,0.806 6.956,0.55 7.05,0.2
  Top Layer region: 4.51,-0.2 4.416,-0.55 4.16,-0.806 3.81,-0.9 3.46,-0.806 3.204,-0.55 3.11,-0.2 3.11,0.2 3.204,0.55 3.46,0.806 3.81,0.9 4.16,0.806 4.416,0.55 4.51,0.2
  Top Layer region: 1.97,-0.2 1.876,-0.55 1.62,-0.806 1.27,-0.9 0.92,-0.806 0.664,-0.55 0.57,-0.2 0.57,0.2 0.664,0.55 0.92,0.806 1.27,0.9 1.62,0.806 1.876,0.55 1.97,0.2
  Top Layer region: -0.57,-0.2 -0.664,-0.55 -0.92,-0.806 -1.27,-0.9 -1.62,-0.806 -1.876,-0.55 -1.97,-0.2 -1.97,0.2 -1.876,0.55 -1.62,0.806 -1.27,0.9 -0.92,0.806 -0.664,0.55 -0.57,0.2
  Top Layer region: -3.11,-0.2 -3.204,-0.55 -3.46,-0.806 -3.81,-0.9 -4.16,-0.806 -4.416,-0.55 -4.51,-0.2 -4.51,0.2 -4.416,0.55 -4.16,0.806 -3.81,0.9 -3.46,0.806 -3.204,0.55 -3.11,0.2
  Top Layer region: -5.65,-0.2 -5.744,-0.55 -6,-0.806 -6.35,-0.9 -6.7,-0.806 -6.956,-0.55 -7.05,-0.2 -7.05,0.2 -6.956,0.55 -6.7,0.806 -6.35,0.9 -6,0.806 -5.744,0.55 -5.65,0.2
  Bottom Layer region: 9.59,-0.2 9.496,-0.55 9.24,-0.806 8.89,-0.9 8.54,-0.806 8.284,-0.55 8.19,-0.2 8.19,0.2 8.284,0.55 8.54,0.806 8.89,0.9 9.24,0.806 9.496,0.55 9.59,0.2
  Bottom Layer region: 7.05,-0.2 6.956,-0.55 6.7,-0.806 6.35,-0.9 6,-0.806 5.744,-0.55 5.65,-0.2 5.65,0.2 5.744,0.55 6,0.806 6.35,0.9 6.7,0.806 6.956,0.55 7.05,0.2
  Bottom Layer region: 4.51,-0.2 4.416,-0.55 4.16,-0.806 3.81,-0.9 3.46,-0.806 3.204,-0.55 3.11,-0.2 3.11,0.2 3.204,0.55 3.46,0.806 3.81,0.9 4.16,0.806 4.416,0.55 4.51,0.2
  Bottom Layer region: 1.97,-0.2 1.876,-0.55 1.62,-0.806 1.27,-0.9 0.92,-0.806 0.664,-0.55 0.57,-0.2 0.57,0.2 0.664,0.55 0.92,0.806 1.27,0.9 1.62,0.806 1.876,0.55 1.97,0.2
  Bottom Layer region: -0.57,-0.2 -0.664,-0.55 -0.92,-0.806 -1.27,-0.9 -1.62,-0.806 -1.876,-0.55 -1.97,-0.2 -1.97,0.2 -1.876,0.55 -1.62,0.806 -1.27,0.9 -0.92,0.806 -0.664,0.55 -0.57,0.2
  Bottom Layer region: -3.11,-0.2 -3.204,-0.55 -3.46,-0.806 -3.81,-0.9 -4.16,-0.806 -4.416,-0.55 -4.51,-0.2 -4.51,0.2 -4.416,0.55 -4.16,0.806 -3.81,0.9 -3.46,0.806 -3.204,0.55 -3.11,0.2
  Bottom Layer region: -5.65,-0.2 -5.744,-0.55 -6,-0.806 -6.35,-0.9 -6.7,-0.806 -6.956,-0.55 -7.05,-0.2 -7.05,0.2 -6.956,0.55 -6.7,0.806 -6.35,0.9 -6,0.806 -5.744,0.55 -5.65,0.2
  Multi-Layer region: 9.59,-0.2 9.496,-0.55 9.24,-0.806 8.89,-0.9 8.54,-0.806 8.284,-0.55 8.19,-0.2 8.19,0.2 8.284,0.55 8.54,0.806 8.89,0.9 9.24,0.806 9.496,0.55 9.59,0.2
  Multi-Layer region: 7.05,-0.2 6.956,-0.55 6.7,-0.806 6.35,-0.9 6,-0.806 5.744,-0.55 5.65,-0.2 5.65,0.2 5.744,0.55 6,0.806 6.35,0.9 6.7,0.806 6.956,0.55 7.05,0.2
  Multi-Layer region: 4.51,-0.2 4.416,-0.55 4.16,-0.806 3.81,-0.9 3.46,-0.806 3.204,-0.55 3.11,-0.2 3.11,0.2 3.204,0.55 3.46,0.806 3.81,0.9 4.16,0.806 4.416,0.55 4.51,0.2
  Multi-Layer region: 1.97,-0.2 1.876,-0.55 1.62,-0.806 1.27,-0.9 0.92,-0.806 0.664,-0.55 0.57,-0.2 0.57,0.2 0.664,0.55 0.92,0.806 1.27,0.9 1.62,0.806 1.876,0.55 1.97,0.2
  Multi-Layer region: -0.57,-0.2 -0.664,-0.55 -0.92,-0.806 -1.27,-0.9 -1.62,-0.806 -1.876,-0.55 -1.97,-0.2 -1.97,0.2 -1.876,0.55 -1.62,0.806 -1.27,0.9 -0.92,0.806 -0.664,0.55 -0.57,0.2
  Multi-Layer region: -3.11,-0.2 -3.204,-0.55 -3.46,-0.806 -3.81,-0.9 -4.16,-0.806 -4.416,-0.55 -4.51,-0.2 -4.51,0.2 -4.416,0.55 -4.16,0.806 -3.81,0.9 -3.46,0.806 -3.204,0.55 -3.11,0.2
  Multi-Layer region: -5.65,-0.2 -5.744,-0.55 -6,-0.806 -6.35,-0.9 -6.7,-0.806 -6.956,-0.55 -7.05,-0.2 -7.05,0.2 -6.956,0.55 -6.7,0.806 -6.35,0.9 -6,0.806 -5.744,0.55 -5.65,0.2
  silkscreen extent -10.16,-1.17 10.16,1.27
"FEMALE HEADER 1X10" [mm]
  rect 1.4x1.8 hole 0.7 slot 1 at 90 deg: 1(11.43,0)
  oval 0.6x0.42 hole 0.7 slot 1 at 90 deg: 2(8.89,0) 3(6.35,0) 4(3.81,0) 5(1.27,0) 6(-1.27,0) 7(-3.81,0) 8(-6.35,0) 9(-8.89,0) 10(-11.43,0)
  Top Layer region: -12.13,0.2 -12.036,0.55 -11.78,0.806 -11.43,0.9 -11.08,0.806 -10.824,0.55 -10.73,0.2 -10.73,-0.2 -10.824,-0.55 -11.08,-0.806 -11.43,-0.9 -11.78,-0.806 -12.036,-0.55 -12.13,-0.2
  Top Layer region: -9.59,0.2 -9.496,0.55 -9.24,0.806 -8.89,0.9 -8.54,0.806 -8.284,0.55 -8.19,0.2 -8.19,-0.2 -8.284,-0.55 -8.54,-0.806 -8.89,-0.9 -9.24,-0.806 -9.496,-0.55 -9.59,-0.2
  Top Layer region: -7.05,0.2 -6.956,0.55 -6.7,0.806 -6.35,0.9 -6,0.806 -5.744,0.55 -5.65,0.2 -5.65,-0.2 -5.744,-0.55 -6,-0.806 -6.35,-0.9 -6.7,-0.806 -6.956,-0.55 -7.05,-0.2
  Top Layer region: -4.51,0.2 -4.416,0.55 -4.16,0.806 -3.81,0.9 -3.46,0.806 -3.204,0.55 -3.11,0.2 -3.11,-0.2 -3.204,-0.55 -3.46,-0.806 -3.81,-0.9 -4.16,-0.806 -4.416,-0.55 -4.51,-0.2
  Top Layer region: -1.97,0.2 -1.876,0.55 -1.62,0.806 -1.27,0.9 -0.92,0.806 -0.664,0.55 -0.57,0.2 -0.57,-0.2 -0.664,-0.55 -0.92,-0.806 -1.27,-0.9 -1.62,-0.806 -1.876,-0.55 -1.97,-0.2
  Top Layer region: 0.57,0.2 0.664,0.55 0.92,0.806 1.27,0.9 1.62,0.806 1.876,0.55 1.97,0.2 1.97,-0.2 1.876,-0.55 1.62,-0.806 1.27,-0.9 0.92,-0.806 0.664,-0.55 0.57,-0.2
  Top Layer region: 3.11,0.2 3.204,0.55 3.46,0.806 3.81,0.9 4.16,0.806 4.416,0.55 4.51,0.2 4.51,-0.2 4.416,-0.55 4.16,-0.806 3.81,-0.9 3.46,-0.806 3.204,-0.55 3.11,-0.2
  Top Layer region: 5.65,0.2 5.744,0.55 6,0.806 6.35,0.9 6.7,0.806 6.956,0.55 7.05,0.2 7.05,-0.2 6.956,-0.55 6.7,-0.806 6.35,-0.9 6,-0.806 5.744,-0.55 5.65,-0.2
  Top Layer region: 8.19,0.2 8.284,0.55 8.54,0.806 8.89,0.9 9.24,0.806 9.496,0.55 9.59,0.2 9.59,-0.2 9.496,-0.55 9.24,-0.806 8.89,-0.9 8.54,-0.806 8.284,-0.55 8.19,-0.2
  Bottom Layer region: -12.13,0.2 -12.036,0.55 -11.78,0.806 -11.43,0.9 -11.08,0.806 -10.824,0.55 -10.73,0.2 -10.73,-0.2 -10.824,-0.55 -11.08,-0.806 -11.43,-0.9 -11.78,-0.806 -12.036,-0.55 -12.13,-0.2
  Bottom Layer region: -9.59,0.2 -9.496,0.55 -9.24,0.806 -8.89,0.9 -8.54,0.806 -8.284,0.55 -8.19,0.2 -8.19,-0.2 -8.284,-0.55 -8.54,-0.806 -8.89,-0.9 -9.24,-0.806 -9.496,-0.55 -9.59,-0.2
  Bottom Layer region: -7.05,0.2 -6.956,0.55 -6.7,0.806 -6.35,0.9 -6,0.806 -5.744,0.55 -5.65,0.2 -5.65,-0.2 -5.744,-0.55 -6,-0.806 -6.35,-0.9 -6.7,-0.806 -6.956,-0.55 -7.05,-0.2
  Bottom Layer region: -4.51,0.2 -4.416,0.55 -4.16,0.806 -3.81,0.9 -3.46,0.806 -3.204,0.55 -3.11,0.2 -3.11,-0.2 -3.204,-0.55 -3.46,-0.806 -3.81,-0.9 -4.16,-0.806 -4.416,-0.55 -4.51,-0.2
  Bottom Layer region: -1.97,0.2 -1.876,0.55 -1.62,0.806 -1.27,0.9 -0.92,0.806 -0.664,0.55 -0.57,0.2 -0.57,-0.2 -0.664,-0.55 -0.92,-0.806 -1.27,-0.9 -1.62,-0.806 -1.876,-0.55 -1.97,-0.2
  Bottom Layer region: 0.57,0.2 0.664,0.55 0.92,0.806 1.27,0.9 1.62,0.806 1.876,0.55 1.97,0.2 1.97,-0.2 1.876,-0.55 1.62,-0.806 1.27,-0.9 0.92,-0.806 0.664,-0.55 0.57,-0.2
  Bottom Layer region: 3.11,0.2 3.204,0.55 3.46,0.806 3.81,0.9 4.16,0.806 4.416,0.55 4.51,0.2 4.51,-0.2 4.416,-0.55 4.16,-0.806 3.81,-0.9 3.46,-0.806 3.204,-0.55 3.11,-0.2
  Bottom Layer region: 5.65,0.2 5.744,0.55 6,0.806 6.35,0.9 6.7,0.806 6.956,0.55 7.05,0.2 7.05,-0.2 6.956,-0.55 6.7,-0.806 6.35,-0.9 6,-0.806 5.744,-0.55 5.65,-0.2
  Bottom Layer region: 8.19,0.2 8.284,0.55 8.54,0.806 8.89,0.9 9.24,0.806 9.496,0.55 9.59,0.2 9.59,-0.2 9.496,-0.55 9.24,-0.806 8.89,-0.9 8.54,-0.806 8.284,-0.55 8.19,-0.2
  Multi-Layer region: -12.13,0.2 -12.036,0.55 -11.78,0.806 -11.43,0.9 -11.08,0.806 -10.824,0.55 -10.73,0.2 -10.73,-0.2 -10.824,-0.55 -11.08,-0.806 -11.43,-0.9 -11.78,-0.806 -12.036,-0.55 -12.13,-0.2
  Multi-Layer region: -9.59,0.2 -9.496,0.55 -9.24,0.806 -8.89,0.9 -8.54,0.806 -8.284,0.55 -8.19,0.2 -8.19,-0.2 -8.284,-0.55 -8.54,-0.806 -8.89,-0.9 -9.24,-0.806 -9.496,-0.55 -9.59,-0.2
  Multi-Layer region: -7.05,0.2 -6.956,0.55 -6.7,0.806 -6.35,0.9 -6,0.806 -5.744,0.55 -5.65,0.2 -5.65,-0.2 -5.744,-0.55 -6,-0.806 -6.35,-0.9 -6.7,-0.806 -6.956,-0.55 -7.05,-0.2
  Multi-Layer region: -4.51,0.2 -4.416,0.55 -4.16,0.806 -3.81,0.9 -3.46,0.806 -3.204,0.55 -3.11,0.2 -3.11,-0.2 -3.204,-0.55 -3.46,-0.806 -3.81,-0.9 -4.16,-0.806 -4.416,-0.55 -4.51,-0.2
  Multi-Layer region: -1.97,0.2 -1.876,0.55 -1.62,0.806 -1.27,0.9 -0.92,0.806 -0.664,0.55 -0.57,0.2 -0.57,-0.2 -0.664,-0.55 -0.92,-0.806 -1.27,-0.9 -1.62,-0.806 -1.876,-0.55 -1.97,-0.2
  Multi-Layer region: 0.57,0.2 0.664,0.55 0.92,0.806 1.27,0.9 1.62,0.806 1.876,0.55 1.97,0.2 1.97,-0.2 1.876,-0.55 1.62,-0.806 1.27,-0.9 0.92,-0.806 0.664,-0.55 0.57,-0.2
  Multi-Layer region: 3.11,0.2 3.204,0.55 3.46,0.806 3.81,0.9 4.16,0.806 4.416,0.55 4.51,0.2 4.51,-0.2 4.416,-0.55 4.16,-0.806 3.81,-0.9 3.46,-0.806 3.204,-0.55 3.11,-0.2
  Multi-Layer region: 5.65,0.2 5.744,0.55 6,0.806 6.35,0.9 6.7,0.806 6.956,0.55 7.05,0.2 7.05,-0.2 6.956,-0.55 6.7,-0.806 6.35,-0.9 6,-0.806 5.744,-0.55 5.65,-0.2
  Multi-Layer region: 8.19,0.2 8.284,0.55 8.54,0.806 8.89,0.9 9.24,0.806 9.496,0.55 9.59,0.2 9.59,-0.2 9.496,-0.55 9.24,-0.806 8.89,-0.9 8.54,-0.806 8.284,-0.55 8.19,-0.2
  silkscreen extent -12.67,-1.27 12.7,1.17
HDR1X2 [mm]
  rect 1.8x1.8 hole 1: 1(0,0)
  round 1.8 hole 1: 2(2.54,0)
  silkscreen extent -1.27,-1.27 3.81,1.27
"HDR1X4 - TOP" [mm]
  rect 1.5x1.5 smd: 1(0,0)
  round 1.5 smd: 2(-2.54,0) 3(-5.08,0) 4(-7.62,0)
HDR1X5 [mm]
  rect 1.8x1.8 hole 1: 1(0,0)
  round 1.8 hole 1: 2(2.54,0) 3(5.08,0) 4(7.62,0) 5(10.16,0)
  silkscreen extent -1.27,-1.27 11.43,1.27
HDR2X4 [mm]
  rect 1.8x1.8 hole 1 slot 1.005 at 0 deg: 1(0,0)
  round 1.8 hole 1 slot 1.005 at 0 deg: 2(0,2.54) 3(2.54,0) 4(2.54,2.54) 5(5.08,0) 6(5.08,2.54) 7(7.62,0) 8(7.62,2.54)
  silkscreen extent -1.27,-1.27 8.89,3.81
HDR2X5#1 [mm]
  rect 1.5x1.5 hole 0.9: 1(0,0)
  round 1.5 hole 0.9: 2(0,2.54) 3(2.54,0) 4(2.54,2.54) 5(5.08,0) 6(5.08,2.54) 7(7.62,0) 8(7.62,2.54) 9(10.16,0) 10(10.16,2.54)
  silkscreen extent -1.27,-1.27 11.43,3.81
HDR2X5#2 [mm]
  rect 1.8x1.8 hole 1: 1(0,0)
  round 1.8 hole 1: 2(0,2.54) 3(2.54,0) 4(2.54,2.54) 5(5.08,0) 6(5.08,2.54) 7(7.62,0) 8(7.62,2.54) 9(10.16,0) 10(10.16,2.54)
  silkscreen extent -1.27,-1.27 11.43,3.81
HDR_2.54_2X36 [mm]
  round 1.8 hole 1.1: 1(-44.45,-1.27) 2(-44.45,1.27) 3(-41.91,-1.27) 4(-41.91,1.27) 5(-39.37,-1.27) 6(-39.37,1.27) 7(-36.83,-1.27) 8(-36.83,1.27) 9(-34.29,-1.27) 10(-34.29,1.27) 11(-31.75,-1.27) 12(-31.75,1.27) 13(-29.21,-1.27) 14(-29.21,1.27) 15(-26.67,-1.27) 16(-26.67,1.27) 17(-24.13,-1.27) 18(-24.13,1.27) 19(-21.59,-1.27) 20(-21.59,1.27) 21(-19.05,-1.27) 22(-19.05,1.27) 23(-16.51,-1.27) 24(-16.51,1.27) 25(-13.97,-1.27) 26(-13.97,1.27) 27(-11.43,-1.27) 28(-11.43,1.27) 29(-8.89,-1.27) 30(-8.89,1.27) 31(-6.35,-1.27) 32(-6.35,1.27) 33(-3.81,-1.27) 34(-3.81,1.27) 35(-1.27,-1.27) 36(-1.27,1.27) 37(1.27,-1.27) 38(1.27,1.27) 39(3.81,-1.27) 40(3.81,1.27) 41(6.35,-1.27) 42(6.35,1.27) 43(8.89,-1.27) 44(8.89,1.27) 45(11.43,-1.27) 46(11.43,1.27) 47(13.97,-1.27) 48(13.97,1.27) 49(16.51,-1.27) 50(16.51,1.27) 51(19.05,-1.27) 52(19.05,1.27) 53(21.59,-1.27) 54(21.59,1.27) 55(24.13,-1.27) 56(24.13,1.27) 57(26.67,-1.27) 58(26.67,1.27) 59(29.21,-1.27) 60(29.21,1.27) 61(31.75,-1.27) 62(31.75,1.27) 63(34.29,-1.27) 64(34.29,1.27) 65(36.83,-1.27) 66(36.83,1.27) 67(39.37,-1.27) 68(39.37,1.27) 69(41.91,-1.27) 70(41.91,1.27) 71(44.45,-1.27) 72(44.45,1.27)
  silkscreen extent -45.72,-2.54 45.72,2.54
"HEADER 1X2" [mm]
  rect 1.8x1.8 hole 1 slot 1.005 at 0 deg: 1(0,0)
  round 1.8 hole 1 slot 1.005 at 0 deg: 2(2.54,0)
  silkscreen extent -1.27,-1.27 3.81,1.27
"HEADER 1X3" [mm]
  rect 1.8x1.8 hole 1 slot 1.005 at 0 deg: 1(0,0)
  round 1.8 hole 1 slot 1.005 at 0 deg copper offset 0,0: 2(2.54,0) 3(5.08,0)
  silkscreen extent -1.27,-1.27 6.35,1.27
IMPORTED_IMAGE [mil]
  silkscreen extent 0,0 315,315
LED0603 [mil]
  rect 36x32 smd: 1(-0.04,0.2) 2(60.96,0.2)
  silkscreen extent -28,-28 110,27
"LQFP48 - 2" [mm]
  rect 1.2x0.3 smd: 1(0,0) 2(0,-0.5) 3(0,-1) 4(0,-1.5) 5(0,-2) 6(0,-2.5) 7(0,-3) 8(0,-3.5) 9(0,-4) 10(0,-4.5) 11(0,-5) 12(0,-5.5) 25(8.5,-5.5) 26(8.5,-5) 27(8.5,-4.5) 28(8.5,-4) 29(8.5,-3.5) 30(8.5,-3) 31(8.5,-2.5) 32(8.5,-2) 33(8.5,-1.5) 34(8.5,-1) 35(8.5,-0.5) 36(8.5,0)
  rect 0.3x1.2 smd: 13(1.5,-7) 14(2,-7) 15(2.5,-7) 16(3,-7) 17(3.5,-7) 18(4,-7) 19(4.5,-7) 20(5,-7) 21(5.5,-7) 22(6,-7) 23(6.5,-7) 24(7,-7) 37(7,1.5) 38(6.5,1.5) 39(6,1.5) 40(5.5,1.5) 41(5,1.5) 42(4.5,1.5) 43(4,1.5) 44(3.5,1.5) 45(3,1.5) 46(2.5,1.5) 47(2,1.5) 48(1.5,1.5)
  silkscreen extent -0.12,-5.71 7.11,0.89
LQFP48_7*7 [mm]
  rect 1.2x0.3 smd: 1(-4.25,2.75) 2(-4.25,2.25) 3(-4.25,1.75) 4(-4.25,1.25) 5(-4.25,0.75) 6(-4.25,0.25) 7(-4.25,-0.25) 8(-4.25,-0.75) 9(-4.25,-1.25) 10(-4.25,-1.75) 11(-4.25,-2.25) 12(-4.25,-2.75) 25(4.25,-2.75) 26(4.25,-2.25) 27(4.25,-1.75) 28(4.25,-1.25) 29(4.25,-0.75) 30(4.25,-0.25) 31(4.25,0.25) 32(4.25,0.75) 33(4.25,1.25) 34(4.25,1.75) 35(4.25,2.25) 36(4.25,2.75)
  rect 0.3x1.2 smd: 13(-2.75,-4.25) 14(-2.25,-4.25) 15(-1.75,-4.25) 16(-1.25,-4.25) 17(-0.75,-4.25) 18(-0.25,-4.25) 19(0.25,-4.25) 20(0.75,-4.25) 21(1.25,-4.25) 22(1.75,-4.25) 23(2.25,-4.25) 24(2.75,-4.25) 37(2.75,4.25) 38(2.25,4.25) 39(1.75,4.25) 40(1.25,4.25) 41(0.75,4.25) 42(0.25,4.25) 43(-0.25,4.25) 44(-0.75,4.25) 45(-1.25,4.25) 46(-1.75,4.25) 47(-2.25,4.25) 48(-2.75,4.25)
  silkscreen extent -4.37,-2.96 2.86,3.64
LQFP144_20*20 [mm]
  rect 1.35x0.3 smd: 1(-10.625,8.75) 2(-10.625,8.25) 3(-10.625,7.75) 4(-10.625,7.25) 5(-10.625,6.75) 6(-10.625,6.25) 7(-10.625,5.75) 8(-10.625,5.25) 9(-10.625,4.75) 10(-10.625,4.25) 11(-10.625,3.75) 12(-10.625,3.25) 13(-10.625,2.75) 14(-10.625,2.25) 15(-10.625,1.75) 16(-10.625,1.25) 17(-10.625,0.75) 18(-10.625,0.25) 19(-10.625,-0.25) 20(-10.625,-0.75) 21(-10.625,-1.25) 22(-10.625,-1.75) 23(-10.625,-2.25) 24(-10.625,-2.75) 25(-10.625,-3.25) 26(-10.625,-3.75) 27(-10.625,-4.25) 28(-10.625,-4.75) 29(-10.625,-5.25) 30(-10.625,-5.75) 31(-10.625,-6.25) 32(-10.625,-6.75) 33(-10.625,-7.25) 34(-10.625,-7.75) 35(-10.625,-8.25) 36(-10.625,-8.75) 73(10.625,-8.75) 74(10.625,-8.25) 75(10.625,-7.75) 76(10.625,-7.25) 77(10.625,-6.75) 78(10.625,-6.25) 79(10.625,-5.75) 80(10.625,-5.25) 81(10.625,-4.75) 82(10.625,-4.25) 83(10.625,-3.75) 84(10.625,-3.25) 85(10.625,-2.75) 86(10.625,-2.25) 87(10.625,-1.75) 88(10.625,-1.25) 89(10.625,-0.75) 90(10.625,-0.25) 91(10.625,0.25) 92(10.625,0.75) 93(10.625,1.25) 94(10.625,1.75) 95(10.625,2.25) 96(10.625,2.75) 97(10.625,3.25) 98(10.625,3.75) 99(10.625,4.25) 100(10.625,4.75) 101(10.625,5.25) 102(10.625,5.75) 103(10.625,6.25) 104(10.625,6.75) 105(10.625,7.25) 106(10.625,7.75) 107(10.625,8.25) 108(10.625,8.75)
  rect 0.3x1.35 smd: 37(-8.75,-10.625) 38(-8.25,-10.625) 39(-7.75,-10.625) 40(-7.25,-10.625) 41(-6.75,-10.625) 42(-6.25,-10.625) 43(-5.75,-10.625) 44(-5.25,-10.625) 45(-4.75,-10.625) 46(-4.25,-10.625) 47(-3.75,-10.625) 48(-3.25,-10.625) 49(-2.75,-10.625) 50(-2.25,-10.625) 51(-1.75,-10.625) 52(-1.25,-10.625) 53(-0.75,-10.625) 54(-0.25,-10.625) 55(0.25,-10.625) 56(0.75,-10.625) 57(1.25,-10.625) 58(1.75,-10.625) 59(2.25,-10.625) 60(2.75,-10.625) 61(3.25,-10.625) 62(3.75,-10.625) 63(4.25,-10.625) 64(4.75,-10.625) 65(5.25,-10.625) 66(5.75,-10.625) 67(6.25,-10.625) 68(6.75,-10.625) 69(7.25,-10.625) 70(7.75,-10.625) 71(8.25,-10.625) 72(8.75,-10.625) 109(8.75,10.625) 110(8.25,10.625) 111(7.75,10.625) 112(7.25,10.625) 113(6.75,10.625) 114(6.25,10.625) 115(5.75,10.625) 116(5.25,10.625) 117(4.75,10.625) 118(4.25,10.625) 119(3.75,10.625) 120(3.25,10.625) 121(2.75,10.625) 122(2.25,10.625) 123(1.75,10.625) 124(1.25,10.625) 125(0.75,10.625) 126(0.25,10.625) 127(-0.25,10.625) 128(-0.75,10.625) 129(-1.25,10.625) 130(-1.75,10.625) 131(-2.25,10.625) 132(-2.75,10.625) 133(-3.25,10.625) 134(-3.75,10.625) 135(-4.25,10.625) 136(-4.75,10.625) 137(-5.25,10.625) 138(-5.75,10.625) 139(-6.25,10.625) 140(-6.75,10.625) 141(-7.25,10.625) 142(-7.75,10.625) 143(-8.25,10.625) 144(-8.75,10.625)
  silkscreen extent -10.75,-8.78 8.68,9.89
OSC-SMD_4P-L3.2-W2.5-BL [mm]
  rect 1.4x1.2 smd: 1(-1.1,-0.875) 2(1.1,-0.875) 3(1.1,0.875) 4(-1.1,0.875)
  silkscreen extent -2.29,-1.9 2.03,1.65
OSC-TH_BD2.0-P0.70-D0.3 [mm]
  round 0.8 hole 0.5: 1(0,0.5) 2(0,-0.5)
  silkscreen extent -7.6,-1 -0.54,1
POWERDI-123_L2.8-W1.8-LS3.7-RD [mm]
  rect 2.4x1.5 smd: 1(-1.187,0)
  rect 1.05x1.5 smd: 2(1.187,0)
  silkscreen extent -2,-1 1.2,1
R0603 [mil]
  rect 31.75x34.02 smd: 1(-29.66,0) 2(29.66,0)
  silkscreen extent -55,-26 55,26
RES-ARRAY-SMD_0603-8P-L3.2-W1.6-BL [mm]
  rect 0.65x0.8 smd: 1(-1.2,-0.9) 4(1.2,-0.9) 5(1.2,0.9) 8(-1.2,0.9)
  rect 0.5x0.8 smd: 2(-0.4,-0.9) 3(0.4,-0.9) 6(0.4,0.9) 7(-0.4,0.9)
  silkscreen extent -1.87,-1.45 1.87,1.47
RJ45-TH_HR911105A [mm]
  rect 1.6x1.6 hole 1: 1(-4.45,4.355)
  round 1.6 hole 1: 2(-3.18,6.895) 3(-1.91,4.355) 4(-0.64,6.895) 5(0.63,4.355) 6(1.9,6.895) 7(3.17,4.355) 8(4.44,6.895)
  round 1.8 hole 1.1: 9(-6.625,-6.895) 10(-4.085,-6.895) 11(4.085,-6.895) 12(6.625,-6.895)
  round 2.5 hole 1.8: SH1(-7.745,1.055) SH2(7.745,1.055)
  Board Outline Layer circle w0.005: c-5.715,-1.995 r1.65
  Board Outline Layer circle w0.005: c5.715,-1.995 r1.65
  Board Outline Layer circle w0.254: c-5.715,-1.995 r1.65
  Board Outline Layer circle w0.254: c5.715,-1.995 r1.65
  Multi-Layer board cut-out: -7.365,-1.995 -7.14,-2.815 -6.537,-3.414 -5.715,-3.633 -4.894,-3.414 -4.29,-2.815 -4.065,-1.995 -4.065,-1.995 -4.29,-1.175 -4.894,-0.576 -5.715,-0.357 -6.536,-0.576 -7.14,-1.175 -7.365,-1.995
  Multi-Layer board cut-out: 4.065,-1.995 4.29,-2.815 4.893,-3.414 5.715,-3.633 6.536,-3.414 7.14,-2.815 7.365,-1.995 7.365,-1.995 7.14,-1.175 6.536,-0.576 5.715,-0.357 4.894,-0.576 4.29,-1.175 4.065,-1.995
  silkscreen extent -8.05,-12.92 8.05,8.68
SB-PAD [mm]
  oval 0.735x0.6 smd: 1(-0.587,0)
  oval 0.791x0.6 smd: 2(0.541,0)
  Top Layer region: -1.2,-0.5 -1.2,0.5 -0.418,0.5 0.025,0 -0.433,-0.5
  Top Layer region: -0.119,0.5 0.381,0 -0.119,-0.5 1.2,-0.5 1.2,0.5
  silkscreen extent -1.28,-0.58 1.28,0.58
SOD-123FL_L2.8-W1.8-LS3.8-RD [mm]
  rect 0.93x1.2 smd: 1(-1.6,0) 2(1.6,0)
  silkscreen extent -1.6,-0.95 1.38,0.95
SOIC-8_208MIL [mm]
  oval 0.7x2.2 smd: 1(-1.905,-3.4) 2(-0.635,-3.4) 3(0.635,-3.4) 4(1.905,-3.4) 5(1.905,3.4) 6(0.635,3.4) 7(-0.635,3.4) 8(-1.905,3.4)
  silkscreen extent -2.95,-3.9 2.5,1.9
SOIC-8_L4.9-W3.9-P1.27-LS6.0-BL [mm]
  oval 0.588x2.045 smd: 1(-1.905,-2.772) 2(-0.635,-2.772) 3(0.635,-2.772) 4(1.905,-2.772) 5(1.905,2.772) 6(0.635,2.772) 7(-0.635,2.772) 8(-1.905,2.772)
  silkscreen extent -2.8,-2.92 2.53,1.52
SOT-23-3_L2.9-W1.3-P1.90-LS2.4-BR [mm]
  rect 1.25x0.7 smd: 1(1,-0.95) 2(1,0.95) 3(-1,0)
  silkscreen extent -0.73,-1.53 0.73,1.53
SOT-23-5 [mil]
  rect 50x20 smd: 1(-65,100) 2(-65,63) 3(-65,25) 4(35,25) 5(35,100)
  silkscreen extent -65,1 18,135
SW-SMD_4P-L6.0-W6.0-P4.50-LS9.0 [mm]
  rect 2.2x1.5 smd: 1(-4.4,2.25) 2(-4.4,-2.25) 3(4.4,2.25) 4(4.4,-2.25)
  silkscreen extent -3,-3 3,3
SW-TH_DSWB01LHGET [mm]
  round 1.6 hole 1: 1(0,3.81) 2(0,-3.81)
  silkscreen extent -2.02,-5.11 2.13,5.05
TESTHOOK [mm]
  rect 2.3x2.3 hole 1.2 slot 1.6 at 0 deg: 1(0,0)
  silkscreen extent -1.8,-1.8 1.8,1.8
USB-A-TH__USB-AF-90 [mm]
  round 1.7 hole 1.1 copper offset 0,0: 1(-3.5,1.355) 2(-1,1.355) 3(1,1.355) 4(3.5,1.355)
  round 3.1 hole 2.1: SH1(7,-1.355) SH2(-7,-1.355)
  silkscreen extent -7.22,-11.51 7.22,2.49
USB-C-SMD_TYPEC-304-BCP16#1 [mil]
  oval 39.4x82.7 hole 23.6 slot 70.9 at 90 deg: 13(-170.1,64.3) 14(170.1,64.3)
  oval 39.4x63 hole 23.6 slot 47.2 at 90 deg: 15(-170.1,-100.3) 16(170.1,-100.3)
  rect 23.6x57.1 smd: A1B12(-127,100.3) A4B9(-96.5,100.3) B1A12(126.8,100.3) B4A9(96.5,100.3)
  rect 11.8x57.1 smd: A5(-49.2,100.3) A6(-9.8,100.3) A7(9.8,100.3) A8(49.2,100.3) B5(68.9,100.3) B6(29.5,100.3) B7(-29.5,100.3) B8(-68.9,100.3)
  Board Outline Layer circle w0.2: c117.3,43.4 r13.8
  Board Outline Layer circle w0.2: c-117.3,43.4 r13.8
  Board Outline Layer circle w10: c117.3,43.4 r13.8
  Board Outline Layer circle w10: c-117.3,43.4 r13.8
  Multi-Layer board cut-out: 117.3,29.6 123.29,30.97 128.09,34.8 130.75,40.33 130.75,46.47 128.09,52.01 123.28,55.84 117.3,57.2 117.3,57.2 110.4,55.35 105.34,50.3 103.5,43.4 105.35,36.5 110.4,31.45 117.3,29.6
  Multi-Layer board cut-out: -117.3,29.6 -111.31,30.97 -106.51,34.8 -103.85,40.33 -103.85,46.47 -106.51,52.01 -111.32,55.84 -117.3,57.2 -117.3,57.2 -124.2,55.35 -129.26,50.3 -131.1,43.4 -129.25,36.5 -124.2,31.45 -117.3,29.6
  silkscreen extent -170,-200 170,120
USB-C-SMD_TYPEC-304-BCP16#2 [mil]
  oval 39.4x82.7 hole 23.6 slot 70.9 at 90 deg: 13(-170.1,64.3) 14(170.1,64.3)
  oval 39.4x63 hole 23.6 slot 47.2 at 90 deg: 15(-170.1,-100.3) 16(170.1,-100.3)
  rect 23.6x57.1 smd: A1B12(-127,100.3) A4B9(-96.5,100.3) B1A12(126.8,100.3) B4A9(96.5,100.3)
  rect 11.8x57.1 smd: A5(-49.2,100.3) A6(-9.8,100.3) A7(9.8,100.3) A8(49.2,100.3) B5(68.9,100.3) B6(29.5,100.3) B7(-29.5,100.3) B8(-68.9,100.3)
  Board Outline Layer circle w0.2: c117.3,43.4 r13.8
  Board Outline Layer circle w0.2: c-117.3,43.4 r13.8
  Board Outline Layer circle w10: c117.3,43.4 r13.8
  Board Outline Layer circle w10: c-117.3,43.4 r13.8
  Multi-Layer board cut-out: 103.5,43.4 105.41,36.58 110.45,31.61 117.3,29.79 124.14,31.61 129.19,36.58 131.1,43.4 131.1,43.4 129.19,50.22 124.14,55.19 117.3,57.01 110.45,55.19 105.41,50.22 103.5,43.4
  Multi-Layer board cut-out: -131.1,43.4 -129.19,36.58 -124.15,31.61 -117.3,29.79 -110.46,31.61 -105.41,36.58 -103.5,43.4 -103.5,43.4 -105.41,50.22 -110.46,55.19 -117.3,57.01 -124.15,55.19 -129.19,50.22 -131.1,43.4
  silkscreen extent -170,-200 170,120

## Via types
v1: diameter 19.7, hole 11.8, Top Layer to Bottom Layer, 489 vias
v2: diameter 19.68, hole 11.81, Top Layer to Bottom Layer, 425 vias
v3: diameter 31.5, hole 19.68, Top Layer to Bottom Layer, 18 vias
